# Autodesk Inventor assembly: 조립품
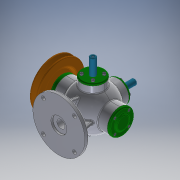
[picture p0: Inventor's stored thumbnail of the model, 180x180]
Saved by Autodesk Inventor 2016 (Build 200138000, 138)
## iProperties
Created: 2019-11
Part Number: 조립품
Material: 일반
Document SubType Name: Assembly
Designer: user
Mass: 3778.23 g
Surface Area: 2410.88 cm^2
Volume: 904.616 cm^3
Density: 4.17662 g/cm^3
Author: user
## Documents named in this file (17)
- C:\Users\user\Desktop\391120V1007\조립품.iam
- C:\Users\user\Desktop\391120V1007\V-벨트풀리.ipt
- C:\Users\user\Desktop\391120V1007\가변스프링.ipt
- C:\Users\user\Desktop\391120V1007\가변스프링2.ipt
- C:\Users\user\Desktop\391120V1007\너트 M8x1.ipt
- C:\Users\user\Desktop\391120V1007\뒤커버.ipt
- C:\Users\user\Desktop\391120V1007\베어링 6202.ipt
- C:\Users\user\Desktop\391120V1007\본체.ipt
- C:\Users\user\Desktop\391120V1007\본체커버.ipt
- C:\Users\user\Desktop\391120V1007\볼트 M4.ipt
- C:\Users\user\Desktop\391120V1007\슬라이드 커버.ipt
- C:\Users\user\Desktop\391120V1007\슬라이드.ipt
- C:\Users\user\Desktop\391120V1007\앞커버.ipt
- C:\Users\user\Desktop\391120V1007\오일 실.ipt
- C:\Users\user\Desktop\391120V1007\와셔 8x17.ipt
- C:\Users\user\Desktop\391120V1007\축.ipt
- C:\Users\user\Desktop\391120V1007\키 4x4.ipt
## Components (3 placed, 3 different names)
1. V-벨트풀리:1 — 플러쉬:2
2. 가변스프링:1
3. 가변스프링2:1
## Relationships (1: Flush 1)
- 플러쉬:2 [Flush]: V-벨트풀리:1
